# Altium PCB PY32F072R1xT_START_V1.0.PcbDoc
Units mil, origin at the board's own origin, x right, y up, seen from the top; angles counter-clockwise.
Board outline 3200 x 1100 mil, 2 copper layers (Top Layer, Bottom Layer); 43 components, 73 nets, 230 pads, 85 vias.
Unrouted connection lines stored in the file: 26.
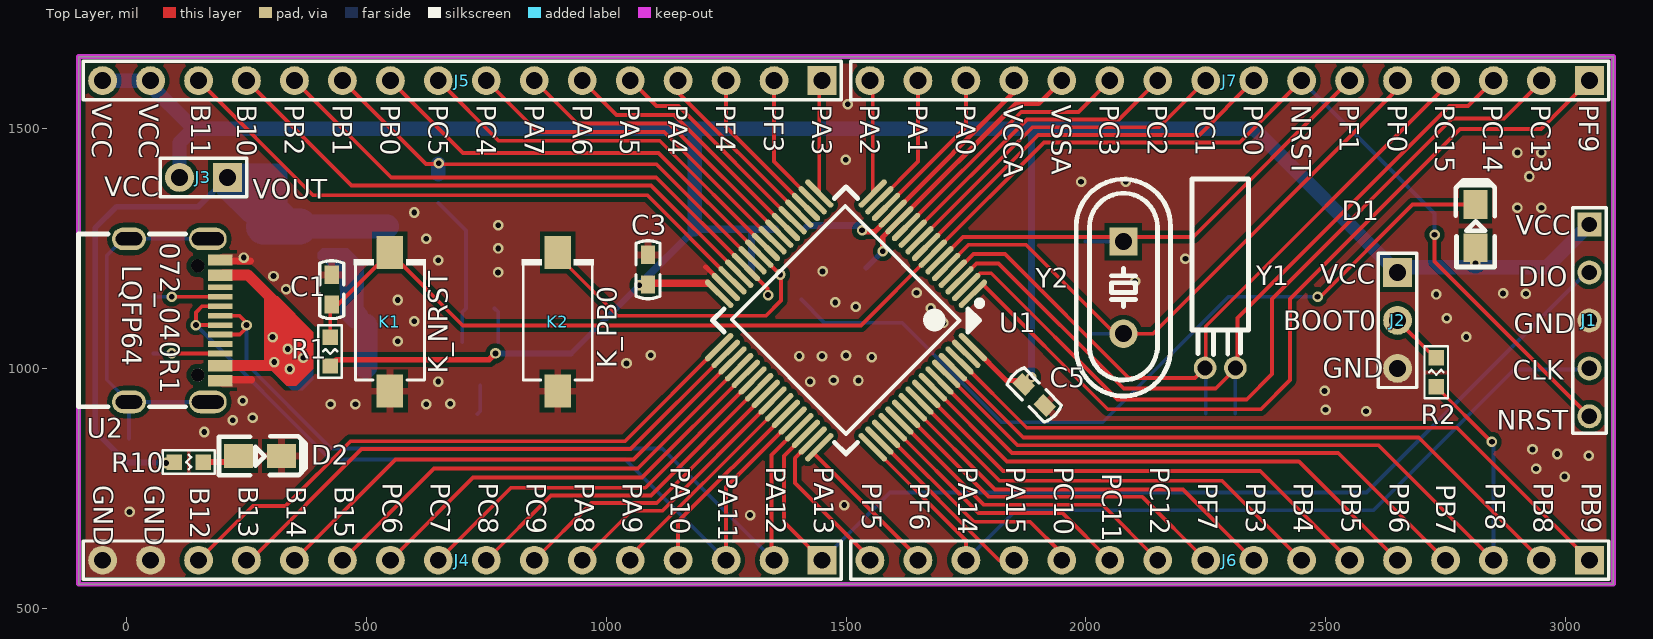
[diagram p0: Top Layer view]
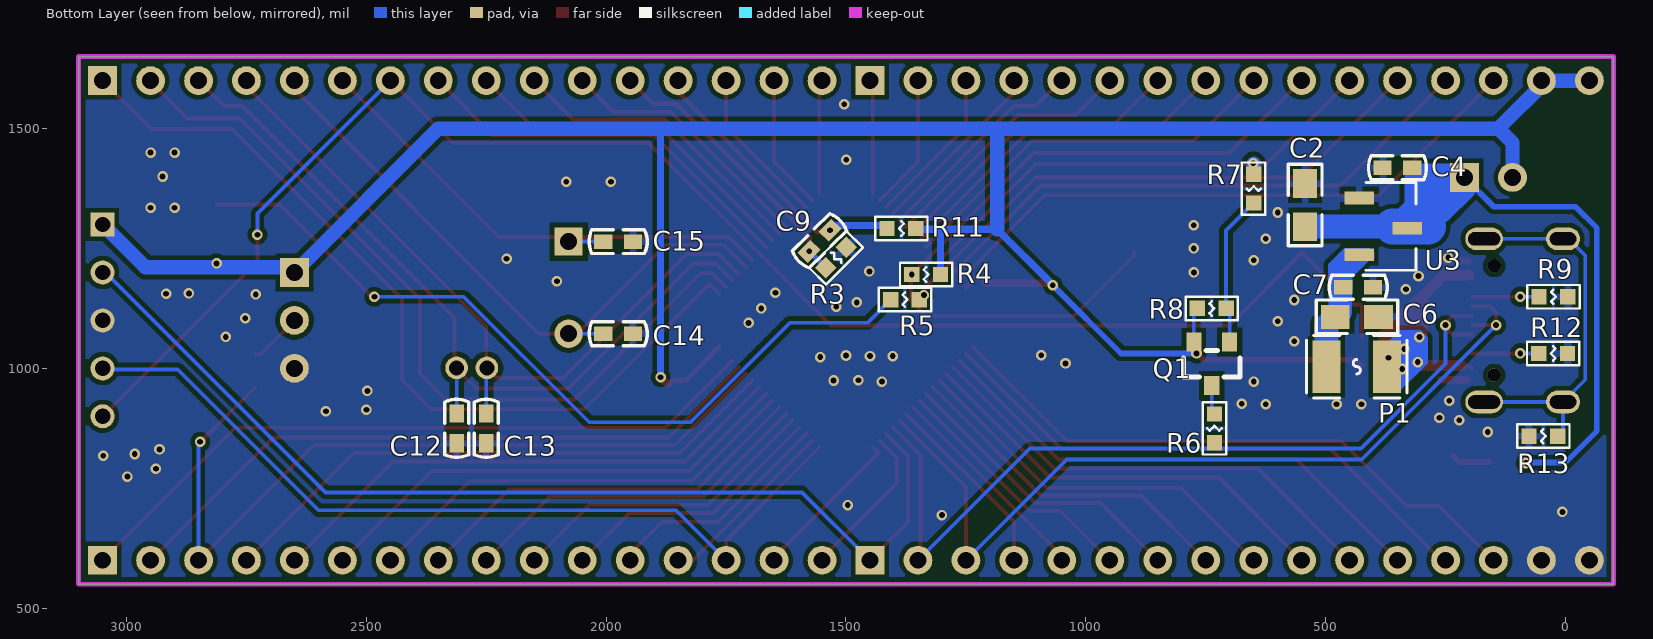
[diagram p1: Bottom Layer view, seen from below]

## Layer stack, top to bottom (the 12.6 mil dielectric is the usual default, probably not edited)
Top Solder: solder mask 0.4, Solder Resist, Dk 3.5
Top Layer: signal copper 1.4
Dielectric1: core 12.6, FR-4, Dk 4.8
Bottom Layer: signal copper 1.4
Bottom Solder: solder mask 0.4, Solder Resist, Dk 3.5

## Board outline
-100,550 -100,1650 3100,1650 3100,550

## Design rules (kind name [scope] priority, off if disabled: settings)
Clearance [All] p1: gap=7 ignorepadtopadclearanceinfootprint=FALSE
ComponentClearance [All] p1: gap=0 collisioncheckmode=3 verticalgap=0 showdistances=FALSE
DiffPairsRouting [All] p1: maxlimit=50 minlimit=1 mostfreqgap=1 toplayer_minwidth=15 toplayer_maxwidth=15 toplayer_prefwidth=15 bottomlayer_minwidth=15 bottomlayer_maxwidth=15 bottomlayer_prefwidth=15 maxuncoupledlength=500
HoleSize [All] p1: absolutevalues=TRUE maxlimit=9999 minlimit=1 maxpercent=80.000 minpercent=20.000
HoleToHoleClearance [All] p1: gap=1 allowstackedmicrovias=TRUE
MinimumSolderMaskSliver [All] p1: minsoldermaskwidth=0
PlaneConnect [All] p1: planeconnectstyle=Relief reliefexpansion=20 reliefentries=4 reliefconductorwidth=15 reliefairgap=10
PolygonConnect [All] p1: thpad.connectstyle=Direct thpad.reliefconductorwidth=15 thpad.reliefentries=4 thpad.polygonreliefangle="90 Angle" thpad.airgapwidth=10 smdpad.connectstyle=Relief smdpad.reliefconductorwidth=15 smdpad.reliefentries=4 smdpad.polygonreliefangle="90 Angle" smdpad.airgapwidth=10 via.connectstyle=Direct via.reliefconductorwidth=15 via.reliefentries=4 via.polygonreliefangle="90 Angle" via.airgapwidth=10
RoutingCorners [All] p1: cornerstyle=45-Degree minsetback=30 maxsetback=1000
RoutingVias [All] p1: holewidth=28 width=50 viastyle="Through Hole" minholewidth=1 minwidth=1 maxholewidth=10000 maxwidth=10000
SilkToSilkClearance [All] p1: silktosilkclearance=0
SilkToSolderMaskClearance [IsPad] p1: minsilkscreentomaskgap=0 clearancetoexposedcopper=TRUE
SolderMaskExpansion [All] p1: expansion=4 istentingtop=FALSE
Width [All] p1: maxlimit=100 minlimit=6 preferedwidth=6
21 further rules are at their usual default settings.

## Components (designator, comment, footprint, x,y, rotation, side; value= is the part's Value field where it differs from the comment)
C1 "100nF" C0603 427.53,1164.21 r270 top
C2 "10uF" C0805 542.65,1340.43 r270 bottom
C3 "100nF" C0603 1087.24,1205.68 r270 top
C4 "100nF" C0603 350.17,1418.35 r180 bottom
C5 "100nF" C0603 1892.59,944.65 r135 top
C6 "10uF" C0805 434.69,1107.58 r0 bottom
C7 "100nF" C0603 432,1168.9 r0 bottom
C9 "100nF" C0603 1555.34,1265.93 r135 bottom
C12 "22pF" C0603 2311.71,875 r270 bottom
C13 "22pF" C0603 2250,875 r270 bottom
C14 "22pF" C0603 1975,1072.24 r180 bottom
C15 "22pF" C0603 1975,1264.37 r180 bottom
D1 "LED" LED-0805 2812.87,1296.61 r270 top
D2 "LED" LED-0805 278.2,817.16 r180 top
J1 "CON5" CON5 3050,1300 r270 top
J2 "CON3" CON3 2650,1200 r270 top
J3 "CON2" CON2 210.37,1398.07 r180 top
J4 "CON16" CON16 1450,600 r180 top locked
J5 "CON16" CON16 1450,1600 r180 top locked
J6 "CON16" CON16 3050,600 r180 top locked
J7 "CON16" CON16 3050,1600 r180 top locked
K1 "1TS002B-2600-5001_key" SW 550,1050 r90 top
K2 "1TS002B-2600-5001_key" SW 900,1050 r90 top
P1 "SMD1210P005TF" SDM1210P005TF 432,981.93 r0 bottom
Q1 "2301" "SOT23 2301" 700,1054.77 r90 bottom value=SI2301
R1 "10K" R0603 424.53,1035.08 r270 top
R2 "10K" R0603 2730.76,991.78 r270 top
R3 "0R" R0603 1520.68,1230.86 r315 bottom
R4 "1.5K" R0603 1332.97,1195.68 r180 bottom
R5 "1K" R0603 1376.98,1143.35 r180 bottom
R6 "1.5K" R0603 731.81,875 r90 bottom
R7 "100R" R0603 650,1374.75 r90 bottom
R8 "100K" R0603 737.4,1125 r180 bottom
R9 "5.1K" R0603 25,1149.21 r180 bottom
R10 "1K" R0603 129.57,804.58 r180 top
R11 "0R" R0603 1384.48,1291.66 r0 bottom
R12 "5.1K" R0603 25.67,1031.1 r0 bottom
R13 "1M" R0603 45.96,858.65 r180 bottom
U1 "PY32F072x" LQFP-64_L10.0-W10.0-P0.50-LS12.0-BL 1500,1100 r135 top locked
U2 "KH-TYPE-C-16P" USB-C-SMD_KH-TYPE-C-16P 100,1100 r270 top locked
U3 "LM1117-3.3" LM1117-3.3 429.93,1355.27 r0 bottom
Y1 "32.768KHz" 32768KHZ_2 2276.17,1124.85 r270 top value=X503225MSB2GI
Y2 "24M" 25MHZ_2 2075,1134.38 r270 top value=X503225MSB2GI

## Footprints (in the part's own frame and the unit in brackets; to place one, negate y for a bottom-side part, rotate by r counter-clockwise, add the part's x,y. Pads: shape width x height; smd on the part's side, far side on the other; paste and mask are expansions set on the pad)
25MHZ_2 [mm]
  rect 1.5x1.5 hole 0.9: 1(-3.302,0.087)
  round 1.5 hole 0.9: 2(1.578,0.087)
  silkscreen extent -6.6,-2.41 4.88,2.59
32768KHZ_2 [mm]
  round 1.2 hole 0.8: 1(3.142,0.903) 2(3.142,-0.697)
  silkscreen extent -6.86,-1.4 2.44,1.6
C0603 [mil]
  rect 38x30 smd: 1(-31,0) 2(31,0)
  silkscreen extent -60,-25 60,25
C0805 [mil]
  rect 60x50 smd: 1(-45,0) 2(45,0)
  silkscreen extent -85,-35 85,35
CON2 [mil]
  rect 60x60 hole 35: 1(0,0)
  round 60 hole 35: 2(100,0)
  silkscreen extent -40,-40 140,40
CON3 [mil]
  rect 60x60 hole 35: 1(0,0)
  round 60 hole 35: 2(100,0) 3(200,0)
  silkscreen extent -40,-40 240,40
CON5 [mil]
  rect 50x50 hole 32: 1(0,0)
  round 50 hole 32: 2(100,0) 3(200,0) 4(300,0) 5(400,0)
  silkscreen extent -35,-35 435,35
CON16 [mil]
  rect 60x60 hole 35: 1(0,0)
  round 60 hole 35: 2(100,0) 3(200,0) 4(300,0) 5(400,0) 6(500,0) 7(600,0) 8(700,0) 9(800,0) 10(900,0) 11(1000,0) 12(1100,0) 13(1200,0) 14(1300,0) 15(1400,0) 16(1500,0)
  silkscreen extent -40,-40 1540,40
LED-0805 [mil]
  rect 60x50 smd: 1(-45,0) 2(45,0)
  silkscreen extent -95,-41 86,40
LM1117-3.3 [mm]
  rect 1.575x0.672 smd: 1(0,0) 2(-2.55,1.598) 3(0,3)
  Top Layer region: -3.64,2.459 -1.785,2.459 -1.741,2.458 -1.696,2.455 -1.652,2.449 -1.608,2.442 -1.565,2.433 -1.522,2.421 -1.479,2.408 -1.437,2.393 -1.396,2.375 -1.356,2.356 -1.317,2.335 -1.279,2.312 -1.241,2.288 -1.206,2.261 -1.171,2.233 -1.138,2.204 -1.106,2.173 -1.075,2.14 -1.047,2.106 -1.019,2.071 -0.994,2.034 -0.97,1.996 -0.948,1.958 -0.928,1.918 -0.91,1.839 0.788,1.839 0.788,1.179 -0.91,1.179 -0.928,1.099 -0.948,1.06 -0.97,1.021 -0.994,0.983 -1.019,0.947 -1.047,0.911 -1.075,0.877 -1.106,0.845 -1.138,0.814 -1.171,0.784 -1.206,0.756 -1.241,0.73 -1.279,0.705 -1.317,0.682 -1.356,0.661 -1.396,0.642 -1.437,0.625 -1.479,0.609 -1.522,0.596 -1.565,0.585 -1.608,0.575 -1.652,0.568 -1.696,0.563 -1.741,0.56 -1.785,0.559 -3.64,0.559 -3.684,0.56 -3.728,0.563 -3.773,0.568 -3.817,0.575 -3.86,0.585 -3.903,0.596 -3.946,0.609 -3.988,0.625 -4.029,0.642 -4.069,0.661 -4.108,0.682 -4.146,0.705 -4.183,0.73 -4.219,0.756 -4.254,0.784 -4.287,0.814 -4.319,0.845 -4.349,0.877 -4.378,0.911 -4.405,0.947 -4.431,0.983 -4.455,1.021 -4.477,1.06 -4.497,1.099 -4.515,1.14 -4.531,1.181 -4.546,1.224 -4.558,1.266 -4.568,1.31 -4.577,1.353 -4.583,1.398 -4.587,1.442 -4.589,1.486 -4.589,1.531 -4.587,1.575 -4.583,1.62 -4.577,1.664 -4.568,1.708 -4.558,1.751 -4.546,1.794 -4.531,1.836 -4.515,1.877 -4.497,1.918 -4.477,1.958 -4.455,1.996 -4.431,2.034 -4.405,2.071 -4.378,2.106 -4.349,2.14 -4.319,2.173 -4.287,2.204 -4.254,2.233 -4.219,2.261 -4.183,2.288 -4.146,2.312 -4.108,2.335 -4.069,2.356 -4.029,2.375 -3.988,2.393 -3.946,2.408 -3.903,2.421 -3.86,2.433 -3.817,2.442 -3.773,2.449 -3.728,2.455 -3.684,2.458
  silkscreen extent -3.01,-0.83 -0.35,3.83
LQFP-64_L10.0-W10.0-P0.50-LS12.0-BL [mm]
  oval 0.3x2 smd: 1(-3.75,-5.75) 2(-3.25,-5.75) 3(-2.75,-5.75) 4(-2.25,-5.75) 5(-1.75,-5.75) 6(-1.25,-5.75) 7(-0.75,-5.75) 8(-0.25,-5.75) 9(0.25,-5.75) 10(0.75,-5.75) 11(1.25,-5.75) 12(1.75,-5.75) 13(2.25,-5.75) 14(2.75,-5.75) 15(3.25,-5.75) 16(3.75,-5.75) 33(3.75,5.75) 34(3.25,5.75) 35(2.75,5.75) 36(2.25,5.75) 37(1.75,5.75) 38(1.25,5.75) 39(0.75,5.75) 40(0.25,5.75) 41(-0.25,5.75) 42(-0.75,5.75) 43(-1.25,5.75) 44(-1.75,5.75) 45(-2.25,5.75) 46(-2.75,5.75) 47(-3.25,5.75) 48(-3.75,5.75)
  oval 2x0.3 smd: 17(5.75,-3.75) 18(5.75,-3.25) 19(5.75,-2.75) 20(5.75,-2.25) 21(5.75,-1.75) 22(5.75,-1.25) 23(5.75,-0.75) 24(5.75,-0.25) 25(5.75,0.25) 26(5.75,0.75) 27(5.75,1.25) 28(5.75,1.75) 29(5.75,2.25) 30(5.75,2.75) 31(5.75,3.25) 32(5.75,3.75) 49(-5.75,3.75) 50(-5.75,3.25) 51(-5.75,2.75) 52(-5.75,2.25) 53(-5.75,1.75) 54(-5.75,1.25) 55(-5.75,0.75) 56(-5.75,0.25) 57(-5.75,-0.25) 58(-5.75,-0.75) 59(-5.75,-1.25) 60(-5.75,-1.75) 61(-5.75,-2.25) 62(-5.75,-2.75) 63(-5.75,-3.25) 64(-5.75,-3.75)
  silkscreen extent -5,-5.79 5,5
R0603 [mil]
  rect 32x32 smd: 1(-30,0) 2(30,0)
  silkscreen extent -55,-25 55,25
SDM1210P005TF [mm]
  rect 1.485x2.781 smd: 1(-1.524,-0.549) 2(1.676,-0.549)
  silkscreen extent -2.59,-2.2 2.74,1.1
"SOT23 2301" [mm]
  rect 1x0.8 smd mask+0.051: 1(0,0) 2(0,1.9) 3(-2.3,0.95)
  silkscreen extent -1.85,-0.55 -0.45,2.45
SW [mm]
  rect 1.74x1.4 smd: 1(-2.476,0.024) 2(4.864,0.024)
  silkscreen extent -1.88,-1.88 4.5,1.93
USB-C-SMD_KH-TYPE-C-16P [mm]
  oval 1.2x2 hole 0.7 slot 1.7 at 90 deg: 1(-4.32,1.765) 2(4.32,1.765)
  oval 1.2x1.8 hole 0.7 slot 1.4 at 90 deg: 3(-4.32,-2.415) 4(4.32,-2.415)
  rect 0.3x1.3 smd: A1(-3.35,2.415) A4(-2.55,2.415) A5(-1.25,2.415) A6(-0.25,2.415) A7(0.25,2.415) A8(1.25,2.415) A9(2.55,2.415) A12(3.35,2.415) B1(3.05,2.415) B4(2.25,2.415) B5(1.75,2.415) B6(0.75,2.415) B7(-0.75,2.415) B8(-1.75,2.415) B9(-2.25,2.415) B12(-3.05,2.415)
  round 0.7 hole 0.7 unplated: ""(-2.89,1.235) ""(2.89,1.235)
  silkscreen extent -4.57,-5.08 4.57,0.57

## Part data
C1 C3 C4 C5 C7 C9 C12 C13 C14 C15: library part C0603
C2 C6: library part C0805
D1 D2: library part LED_0805
K1 K2: BOM_JLCPCB Part Class="Extended Part", BOM_Manufacturer=HYP, BOM_Manufacturer Part=1TS002B-2600-5001_KEY
Q1: library part "MOSFET P", "MOSFET P"
R1 R2 R3 R4 R5 R6 R7 R8 R9 R10 R11 R12 R13: library part R0603
U1: BOM_JLCPCB Part Class="Extended Part", BOM_Manufacturer=ST, BOM_Manufacturer Part=STM32F103VCT6
U2: BOM_JLCPCB Part Class="Extended Part", BOM_Manufacturer="Shenzhen Kinghelm Elec"
Y1: library part CRYSTAL_1, "Crystal"
Y2: library part CRYSTAL, "Crystal"

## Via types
v1: diameter 22, hole 12, Top Layer to Bottom Layer, tented both sides, 85 vias

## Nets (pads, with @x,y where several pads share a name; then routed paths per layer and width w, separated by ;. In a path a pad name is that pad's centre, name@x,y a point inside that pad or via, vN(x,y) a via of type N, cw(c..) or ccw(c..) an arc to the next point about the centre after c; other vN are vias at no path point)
3.3V_OUT: C2.2 C4.2 J3.1 R10.2 U3.2 | length 1525.9
  Top Layer w8: J3.1@197.27,1411.17 J3.1
  Bottom Layer w12: v1@81,803.93 0.01,803.93 -65.54,869.48 -65.54,1292.8 -21.2,1337.15 149.44,1337.15 J3.1
  Bottom Layer w50: J3.1 214.78,1402.49 311.02,1402.49 311.02,1335.36 U3.2@341.78,1304.59 ; J3.1@211.58,1375.4 259.05,1327.93 ; 247.26,1386.68 294.73,1339.21 ; U3.2 U3.2@341.78,1304.59 ; 363.3,1304.59 U3.2@341.78,1304.59 ; C2.2 350.95,1295.43 U3.2@341.78,1304.59
  other v1: 82.39,802.66
BOOT0: J6.3 R2.2 U1.60 | length 1713.9
  Top Layer w8: U1.60 1857.61,839.83 2610.17,839.83 J6.3 ; R2.2 2845.75,846.79 v1(2846.65,846.79)
  Bottom Layer w8: v1(2846.65,846.79) 2850,843.44 J6.3
NetC6_2: C6.2 C7.2 P1.2 U3.3 | length 144.8
  Bottom Layer w50: C7.2@469.49,1162.41 469.49,1117.77 C6.2 ; P1.2 C6.2@497.98,1089.28
NetD1_1: D1.1 R5.1 | length 1699.9
  Top Layer w8: v1(2483.19,1149.15) 2488.68,1149.15 2681.14,1341.61 D1.1
  Bottom Layer w8: R5.1 1455.39,1094.94 1617.21,1094.94 1824.52,887.63 2035.4,887.63 2296.93,1149.15 v1(2483.19,1149.15)
NetD2_2: D2.2 R10.1 | length 78.8
  Top Layer w12: R10.1 220.63,804.58 D2.2
NetJ2_2: J2.2 R2.1 | length 110.4
  Top Layer w8: J2.2 2720.71,1029.29 R2.1@2731.07,1029.29
NetQ1_1: Q1.1 R7.1 R8.2 | length 316.8
  Bottom Layer w8: R7.1 707.4,1287.35 R8.2 700,1117.6 Q1.1
NetQ1_3: Q1.3 R6.2 | length 61.5
  Bottom Layer w8: R6.2 737.4,910.59 Q1.3
NetR9_1: R9.1 U2.A5 | length 140.1
  Top Layer w8: v1(94.13,1149.21) U2.A5
  Bottom Layer w8: R9.1 v1(94.13,1149.21)
NetR12_2: R12.2 U2.B5 | length 139.4
  Top Layer w8: v1(94.13,1031.1) U2.B5
  Bottom Layer w8: R12.2 v1(94.13,1031.1)
NetR13_2: R13.2 U2.1 U2.2 U2.3 U2.4 | length 791.4
  Bottom Layer w8: R13.2@4.56,853.21 4.92,853.57 U2.4 ; U2.2 U2.4 ; U2.1 -6.89,1270.08 -41.37,1235.6 -41.37,976.21 U2.4
NRST: C1.2 J1.5 J7.7 K1.2 R1.1 U1.7 | length 3359.7
  Top Layer w8: R1.1 424.53,1130.22 C1.2 440.75,1133.21 K1.2 701.06,1089.47 1531.23,1089.47 U1.7 1912.63,1470.87 2320.87,1470.87 J7.7 ; v1(2727.16,1278.69) 2727.16,1222.84 J1.5
  Bottom Layer w8: J7.7 2727.16,1322.84 v1(2727.16,1278.69)
OSC32_IN: C12.1 J7.3 U1.3 Y1.1 | length 1656.8
  Top Layer w8: U1.3 1771.97,1218.85 1818.27,1218.85 2079.01,958.11 2271,958.11 2311.71,998.82 Y1.1 2316.08,1005.52 2316.08,1105.15 2758.02,1547.09 2797.09,1547.09 J7.3
  Bottom Layer w8: C12.1 Y1.1
OSC32_OUT: C13.1 J7.4 U1.4 Y1.2 | length 1560.6
  Top Layer w8: U1.4 1725.23,1197.44 1765.94,1238.14 1831.6,1238.14 2089.63,980.11 2227.68,980.11 Y1.2 2250,1002.43 2250,1087.85 2750,1587.85 J7.4
  Bottom Layer w8: Y1.2 2250,999.87 C13.1
OSC_IN: C14.1 J7.5 U1.5 Y2.2 | length 1338.8
  Top Layer w8: U1.5 1755.28,1257.84 1875.38,1257.84 2060.98,1072.24 Y2.2 2140.08,1072.24 2643.81,1575.97 2643.81,1593.81 J7.5
  Bottom Layer w8: C14.1 Y2.2
OSC_OUT: C15.1 J7.6 U1.6 Y2.1 | length 1107.8
  Top Layer w8: U1.6 1743.69,1274.1 2224.1,1274.1 J7.6
  Bottom Layer w8: C15.1@1998.77,1264.37 Y2.1@2096.2,1264.37
PA0: J7.14 U1.14 | length 332.3
  Top Layer w8: U1.14 1750,1503.12 J7.14
PA1: J7.15 U1.15 | length 282.8
  Top Layer w8: U1.15 1650,1430.95 J7.15
PA2: J7.16 U1.16 | length 237.9
  Top Layer w8: J7.16 1555.67,1594.33 U1.16
PA3: J5.1 U1.17 | length 237.9
  Top Layer w8: U1.17 1444.33,1594.33 J5.1
PA4: J5.4 U1.20 | length 381.9
  Top Layer w8: J5.4 1150,1575.27 U1.20
PA5: J5.5 U1.21 | length 459.3
  Top Layer w8: J5.5 1051.96,1600 1105.2,1546.76 1150.68,1546.76 U1.21
PA6: J5.6 U1.22 | length 551.1
  Top Layer w8: J5.6 1021.54,1528.46 1141.13,1528.46 U1.22
PA7: J5.7 U1.23 | length 643
  Top Layer w8: J5.7 939.51,1510.49 1131.28,1510.49 U1.23
PA8: J4.6 U1.41 | length 534.8
  Top Layer w8: J4.6 1053.2,703.2 1117.11,703.2 U1.41
PA9: J4.5 U1.42 | length 447.8
  Top Layer w8: J4.5 1050,608.24 U1.42
PA10: J4.4 U1.43 | length 398.2
  Top Layer w8: J4.4 1150,680.41 U1.43
PA11: J4.3 U1.44 U2.A7 U2.B7 | length 1790.2
  Top Layer w8: U2.A7 v1(144.52,1090.16) 144.52,1116.8 157.25,1129.53 U2.B7 ; J4.3 1250,752.56 U1.44
  Bottom Layer w8: v1(144.52,1090.16) 424.53,810.14 1039.86,810.14 J4.3
PA12: J4.2 R6.1 U1.45 U2.A6 U2.B6 | length 1784.3
  Top Layer w8: U2.B6 236,1070.47 247.99,1082.46 247.99,1097.2 235.35,1109.84 U2.A6 ; J4.2 1344.94,605.06 1344.94,819.67 U1.45
  Bottom Layer w8: v1(250,1090.16) 250,1009.52 426.28,833.24 1116.76,833.24 J4.2
PA13: J1.2 J4.1 U1.46 | length 2163.8
  Top Layer w8: U1.46 1370.64,817.52 1370.64,679.36 J4.1
  Bottom Layer w8: J4.1 1591.5,741.5 2585.44,741.5 3043.94,1200 J1.2
PA14: J1.4 J6.14 U1.49 | length 1781.7
  Top Layer w8: U1.49 1750,641.21 J6.14
  Bottom Layer w8: J6.14 1854.28,704.28 2599.6,704.28 2893.28,997.97 3047.97,997.97 J1.4
PA15: J6.13 U1.50 | length 383.7
  Top Layer w8: U1.50 1819.05,600 J6.13
PB0: J5.10 K2.2 R4.1 U1.26 | length 1563.5
  Top Layer w8: J5.10 701.12,1448.88 1109.36,1448.88 U1.26 v1@1358.24,1200 ; K2.2 899.04,1234.8 1024.2,1109.64 1333.18,1109.64 1364.73,1141.19 v1@1364.73,1193.51
  other v1: 1362.97,1195.68
PB1: J5.11 R7.2 U1.27 | length 1033.6
  Top Layer w8: J5.11 623.98,1426.02 649.25,1426.02 v1(650.69,1427.46) 652.61,1425.54 1104.87,1425.54 U1.27
  Bottom Layer w30: R7.2 v1@650,1426.77
PB2: J5.12 R5.2 U1.28 | length 1181.4
  Top Layer w8: J5.12 551.93,1398.07 1104.49,1398.07 U1.28 1336.02,1166.54 v1@1336.02,1150.68
  other v1: 1337.57,1152.77
PB3: J6.8 U1.55 | length 843
  Top Layer w8: U1.55 1810.9,747.33 2202.67,747.33 J6.8
PB4: J6.7 U1.56 | length 934.8
  Top Layer w8: U1.56 1820.33,765.75 2284.25,765.75 J6.7
PB5: J6.6 U1.57 | length 1026.7
  Top Layer w8: U1.57 1827.56,786.36 2363.64,786.36 J6.6
PB6: J6.5 U1.58 | length 1118.5
  Top Layer w8: U1.58 1835.9,805.87 2444.13,805.87 J6.5
PB7: J6.4 U1.59 | length 1210.3
  Top Layer w8: U1.59 1846.02,823.57 2526.43,823.57 J6.4
PB8: J6.2 U1.61 | length 1394
  Top Layer w8: U1.61 1869.55,855.73 2694.27,855.73 J6.2
PB9: J6.1 U1.62 | length 1489.4
  Top Layer w8: U1.62 1876.79,876.32 2774.11,876.32 J6.1@3052.58,597.85
PB10: J5.13 U1.29 | length 1194
  Top Layer w8: J5.13 468.8,1381.2 1093.53,1381.2 U1.29
PB11: J5.14 U1.30 | length 1285.9
  Top Layer w8: J5.14 388.92,1361.07 1085.81,1361.07 U1.30
PB12: J4.14 U1.33 | length 1269.6
  Top Layer w8: J4.14 263.04,713.04 331.54,713.04 466.51,848 1039.21,848 U1.33
PB13: J4.13 U1.34 | length 1177.7
  Top Layer w8: J4.13 258.39,600 490.16,831.77 1050.82,831.77 U1.34
PB14: J4.12 U1.35 | length 1085.9
  Top Layer w8: J4.12 560.33,810.33 1057.22,810.33 U1.35
PB15: J4.11 U1.36 | length 994
  Top Layer w8: J4.11 641.16,791.16 1065.89,791.16 U1.36
PC0: J7.8 U1.8 | length 826.7
  Top Layer w8: U1.8 1900.78,1486.87 2236.87,1486.87 J7.8
PC1: J7.9 U1.9 | length 734.8
  Top Layer w8: U1.9 1888.95,1502.87 2152.87,1502.87 J7.9
PC2: J7.10 U1.10 | length 643
  Top Layer w8: U1.10 1877.11,1518.87 2068.87,1518.87 J7.10
PC3: J7.11 U1.11 | length 551.1
  Top Layer w8: U1.11 1865.27,1534.87 1984.87,1534.87 J7.11
PC4: J5.8 U1.24 | length 734.8
  Top Layer w8: J5.8 857.21,1492.79 1121.13,1492.79 U1.24
PC5: J5.9 U1.25 | length 826.7
  Top Layer w8: J5.9 775.5,1474.5 1111.59,1474.5 U1.25
PC6: J4.10 U1.37 | length 902.2
  Top Layer w8: J4.10 722.32,772.32 1074.88,772.32 U1.37
PC7: J4.9 U1.38 | length 810.3
  Top Layer w8: J4.9 801.2,751.2 1081.6,751.2 U1.38
PC8: J4.8 U1.39 | length 718.5
  Top Layer w8: J4.8 885.2,735.2 1093.44,735.2 U1.39
PC9: J4.7 U1.40 | length 626.7
  Top Layer w8: J4.7 969.2,719.2 1105.28,719.2 U1.40
PC10: J6.12 U1.51 | length 483.8
  Top Layer w8: U1.51 1766.79,680.1 1883.97,680.1 1950,614.06 J6.12
PC11: J6.11 U1.52 | length 567.4
  Top Layer w8: U1.52 1775.97,698.76 1951.24,698.76 J6.11
PC12: J6.10 U1.53 | length 659.3
  Top Layer w8: U1.53 1786.76,715.8 2034.2,715.8 J6.10
PC13: J7.2 U1.2 | length 1688.6
  Top Layer w8: U1.2 1779.14,1198.19 1802.91,1198.19 2065.96,935.14 2335.47,935.14 2388.26,987.92 2388.26,1144.98 2764.13,1520.85 2872.55,1520.85 2950,1598.3 J7.2
PF3: J5.2 U1.18 | length 282.8
  Top Layer w8: J5.2 1350,1430.95 U1.18
PF4: J5.3 U1.19 | length 332.3
  Top Layer w8: J5.3 1250,1503.12 U1.19
PF5: J6.16 U1.47 | length 329.4
  Top Layer w8: U1.47 1393.7,812.75 1393.7,761.11 1550,604.8 J6.16
PF6: J6.15 U1.48 | length 330
  Top Layer w8: U1.48 1433.19,824.39 1433.19,822.69 1650,605.88 J6.15
PF7: J6.9 U1.54 | length 751.1
  Top Layer w8: U1.54 1798.25,732.16 2117.84,732.16 J6.9
PF9: J7.1 U1.1 | length 1785
  Top Layer w8: U1.1 1784.64,1175.84 2045.72,914.76 2364.99,914.76 2425.62,975.38 2425.62,1144.69 2780.32,1499.39 2949.39,1499.39 J7.1
Type_C: P1.1 U2.A4 U2.A9 U2.B4 U2.B9 | length 480.2
  Top Layer w8: U2.A9 U2.A9@200.47,1005 ; U2.B9 U2.B9@200.99,1194.48
  Top Layer w23: U2.B9@200.99,1194.48 253.13,1194.48 366.34,1081.28 366.34,1044.48 362.18,1040.33 v1(336.22,1040.33) ; U2.A9@217.21,1005.5 307.81,1005.5 314.61,998.7 v1(340.14,998.7) 366.34,1024.89 366.34,1028.02 354.02,1040.33
  other v1: 307.81,1013.06 368.76,1022.15 304.45,1065.16
VCC: C3.2 C5.2 D1.2 J1.1 J2.1 J3.2 J5.15 J5.16 Q1.2 R1.2 R4.2 R8.1 R11.1 U1.32 U1.64 | length 5641.7
  Top Layer w11: U1.64 1834.07,974.73 1862.52,974.73 C5.2
  Top Layer w12: R1.2 437.67,1018.22 756.32,1018.22 v1(769.2,1031.1)
  Top Layer w15: C3.2@1084.45,1177.36 U1.32@1211.2,1177.36 ; C5.2 1871.42,966.57 v1(1886.54,981.7)
  Bottom Layer w8: R8.1 774.8,1117.6 Q1.2
  Bottom Layer w12: v1(769.2,1031.1) 926.68,1031.1 v1(1069.01,1173.42) ; R11.1@1353.01,1290.19 R11.1
  Bottom Layer w15: v1@1070.07,1175.23 1185.04,1290.19 1302.97,1290.19 ; R4.2@1302.97,1201.05 1302.97,1290.19 ; R11.1@1353.01,1290.19 1302.97,1290.19 ; v1(1886.54,981.7) 1886.54,1500
  Bottom Layer w30: J5.16 40.29,1600 140.29,1500 ; J3.2 110.37,1470.07 140.29,1500 ; 1185.04,1290.19 1185.04,1500 ; J2.1 2350,1500 1886.54,1500 1185.04,1500 ; J2.1@2650,1210.67 2960.67,1210.67 J1.1 ; 140.29,1500 1185.04,1500
  other v1: 2812.28,1218.85
VCCA: C9.2 J7.13 R11.2 U1.13 | length 599.6
  Top Layer w10: U1.13 J7.13@1850,1575.27
  Top Layer w11: v1(1533.42,1287.86) 1536.6,1284.67 1559.4,1284.67 U1.13
  Top Layer w12: J7.13@1850,1575.27 J7.13
  Bottom Layer w12: R11.2 R11.2@1422.2,1299.38 ; C9.2@1523.32,1297.95 v1(1533.42,1287.86)
  Bottom Layer w15: R11.2 1420.77,1297.95 C9.2@1523.32,1297.95
VSS: C1.1 C2.1 C3.1 C4.1 C5.1 C6.1 C7.1 C12.2 C13.2 C14.2 C15.2 D2.1 J1.3 J2.3 J4.15 J4.16 K1.1 K2.1 R3.1 R9.2 R12.1 R13.1 U1.31 U1.63 U2.A1 U2.A12 U2.B1 U2.B12 U3.1 | length 172.2
  Top Layer w10: 1207.23,1211.44 U1.31@1250.07,1168.6
  Top Layer w15: U2.B12@202.56,1223.86 258.36,1223.86 ; U2.B1@204.86,976.1 260.67,976.1
  other v1: 1299.96,694.08 6.32,700.64 1496.51,715 2998.28,774.38 2938.84,790.69 3048.8,817.72 2982.74,821.45 2931.33,830.93 161.82,867.29 221.22,892.03 262.64,896.86 2584.39,910.34 2500,913.51 425.44,925 477.14,925 625,925 675,926.34 242.08,932.51 2497.73,953.02 650,972.47 1425,972.47 1474.2,975 1525.8,974.73 1042.33,1010.34 1553.64,1023.45 1402.56,1025.62 1450,1025.62 1092.78,1027.16 1500,1026.87 565.44,1056.46 2793.25,1065.57 1703.21,1094.78 600,1098.42 2752.63,1104.25 1676.86,1125 1520.54,1128.56 1477.43,1137.58 565.44,1142.58 2730.47,1154.12 2917.66,1155.48 2869.93,1156.31 1647.18,1157.87 332.53,1165 2102.7,1181.45 306.38,1192.5 774.56,1200 1451.26,1202.03 650,1225.27 2207.61,1228.54 244.54,1230.92 775,1250 625,1270.08 774.8,1298.5 600,1325 2900,1335 2950,1335 1990.17,1388.94 2083.04,1388.96 2925,1400 1499.24,1435.01 2900,1450 2950,1450 1503.44,1550.91
VSSA: C9.1 J7.12 R3.2 U1.12 | length 587.4
  Top Layer w10: U1.12 1854.43,1551.87 1901.87,1551.87 J7.12
  Top Layer w11: v1(1576.66,1244.01) 1576.66,1274.1 U1.12
  Bottom Layer w11: R3.2 1576.25,1244.01 v1(1576.66,1244.01)
pads on no net: U2. U2.A8 U2.B8

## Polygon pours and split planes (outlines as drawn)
VSS on Top Layer "BOTTOM-GND" (solid, remove dead copper, pour order 0): -100,1648.58 -99.64,1648.94 3100,1648.94 3100,550 -100,550 -100,1648.92
VSS on Bottom Layer "BOTTOM-GND" (solid, remove dead copper, pour order 1): -99.99,1650.01 -99.98,1650 3100,1650 3100,550 -100,550 -100,1650

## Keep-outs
Keep-Out Layer:
  the board outline again, w10

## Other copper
Top Layer:
  region net Type_C: 287.27,1150.58 287.27,1010.55 334.05,963.77 354.11,963.77 389.69,999.35 389.69,1075.69 314.8,1150.58
Bottom Layer:
  region net NetC6_2: 407.95,1250.45 398.97,1241.47 398.97,1229.28 404.29,1223.96 409.91,1223.96 443.96,1189.91 443.96,1163.91 452.2,1155.67 487.56,1155.67 494.35,1162.46 494.35,1217.19 461.09,1250.45
  region net Type_C: 287.27,1065.26 287.27,1010.55 343.89,953.94 367.69,953.94 389.69,975.94 389.69,1034.64 345,1079.33 301.34,1079.33

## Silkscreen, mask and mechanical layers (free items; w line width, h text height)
Top Overlay:
  text "VCC" at -71.83,1552.56 h40 r270
  text "VCC" at 26.39,1551.53 h40 r270
  text "B11" at 134.47,1550.29 h40 r270
  text "B10" at 230.83,1549.27 h40 r270
  text "PB2" at 329.99,1549.27 h40 r270
  text "PB1" at 429.95,1549.27 h40 r270
  text "PB0" at 529.91,1549.27 h40 r270
  text "PC5" at 629.87,1549.27 h40 r270
  text "PC4" at 729.84,1549.27 h40 r270
  text "PA7" at 829.8,1549.27 h40 r270
  text "PA6" at 929.76,1549.27 h40 r270
  text "PA5" at 1029.72,1549.27 h40 r270
  text "PA4" at 1129.68,1549.27 h40 r270
  text "PF4" at 1229.64,1549.27 h40 r270
  text "PF3" at 1329.6,1549.27 h40 r270
  text "PA3" at 1429.56,1549.27 h40 r270
  text "PA2" at 1529.52,1549.27 h40 r270
  text "PA1" at 1629.48,1549.27 h40 r270
  text "PA0" at 1729.44,1549.27 h40 r270
  text "VCCA" at 1829.4,1549.27 h40 r270
  text "VSSA" at 1929.36,1549.27 h40 r270
  text "PC3" at 2029.33,1549.27 h40 r270
  text "PC2" at 2129.29,1549.27 h40 r270
  text "PC1" at 2229.25,1549.27 h40 r270
  text "PC0" at 2329.21,1549.27 h40 r270
  text "NRST" at 2429.17,1549.27 h40 r270
  text "PF1" at 2529.13,1549.27 h40 r270
  text "PF0" at 2629.09,1549.27 h40 r270
  text "PC15" at 2729.05,1549.27 h40 r270
  text "PC14" at 2829.01,1549.27 h40 r270
  text "PC13" at 2928.97,1549.27 h40 r270
  text "PF9" at 3028.93,1549.27 h40 r270
  text "VCC" at -46.75,1359.24 h40
  text "VOUT" at 262.64,1353.47 h40
  text "VCC" at 2896.85,1278.45 h40
  text "072_040R1" at 70.28,1261.41 h40 r270
  text "LQFP64" at -8.54,1215.12 h40 r270
  text "VCC" at 2488.38,1176.68 h40
  text "DIO" at 2901.26,1171.13 h40
  text "BOOT0" at 2411.53,1079.42 h40
  text "GND" at 2892,1072.78 h40
  text "K_PB0" at 1021.54,1000.31 h40 r90
  text "K_NRST" at 670.02,989.29 h40 r90
  text "GND" at 2494.37,980.55 h40
  text "CLK" at 2889.78,975.83 h40
  text "NRST" at 2857.19,872.49 h40
  text "PA10" at 1134.09,794.44 h40 r270
  text "PA12" at 1334.08,794.44 h40 r270
  text "PA13" at 1434.08,794.44 h40 r270
  text "PA14" at 1734.06,794.44 h40 r270
  text "PA15" at 1834.05,794.44 h40 r270
  text "PC10" at 1934.05,794.44 h40 r270
  text "PC12" at 2134.03,794.44 h40 r270
  text "PA11" at 1234.09,781.11 h40 r270
  text "PC11" at 2034.04,781.11 h40 r270
  text "PC6" at 534.13,761.12 h40 r270
  text "PC7" at 634.12,761.12 h40 r270
  text "PC8" at 734.12,761.12 h40 r270
  text "PC9" at 834.11,761.12 h40 r270
  text "PA8" at 934.11,761.12 h40 r270
  text "PA9" at 1034.1,761.12 h40 r270
  text "PF5" at 1534.07,761.12 h40 r270
  text "PF6" at 1634.06,761.12 h40 r270
  text "PF7" at 2234.03,761.12 h40 r270
  text "PB3" at 2334.02,761.12 h40 r270
  text "PB4" at 2434.02,761.12 h40 r270
  text "PB5" at 2534.01,761.12 h40 r270
  text "PB6" at 2634.01,761.12 h40 r270
  text "PF8" at 2833.99,761.12 h40 r270
  text "PB8" at 2933.99,761.12 h40 r270
  text "PB9" at 3033.98,761.12 h40 r270
  text "PB7" at 2731.13,757.99 h40 r270
  text "GND" at -68.56,756.49 h40 r270
  text "GND" at 37.44,756.27 h40 r270
  text "B13" at 234.15,754.45 h40 r270
  text "B14" at 334.14,754.45 h40 r270
  text "B15" at 434.14,754.45 h40 r270
  text "B12" at 133.24,751.93 h40 r270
